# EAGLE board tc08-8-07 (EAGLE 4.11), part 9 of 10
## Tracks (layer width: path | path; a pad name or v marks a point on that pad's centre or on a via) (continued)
T_PWR_CLR\  (via drill 0.61) (continued)
  Top 0.254: v83.22,202.87 82.9,202.55 82.9,190.49 79.09,186.68 79.09,182.55 78.14,181.6 B23.K2 | v79.41,206.68 79.73,207 79.73,221.6 79.41,221.92 79.41,233.03 80.68,234.3 A23.R1 80.68,235.57 80.68,239.38 76.24,243.83 76.24,254.94 73.38,257.8 73.38,259.7 70.2,259.7 v67.98,257.48
  Bottom 0.254: v83.22,202.87 v79.41,206.68 | v67.98,257.48 65.76,257.48 A24.H2
T_REV\  (via drill 0.61)
  Top 0.254: v61.95,185.73 60.04,187.63 60.04,217.48 60.36,217.79 60.36,220.97 60.04,221.29 60.04,243.83 60.36,244.14 60.36,246.37 60.04,246.68 60.04,248.91 | 60.04,248.91 60.04,254.94 59.73,255.26 59.73,256.21 61.63,258.11 61.63,259.7 A24.F2 | 60.04,248.91 v59.73,248.91
  Bottom 0.254: v61.95,185.73 72.74,185.73 74.01,184.46 B23.J2 | v59.73,248.91 79.41,248.91 80.36,247.96 A23.L1
T_SINGLE_UNIT\  (via drill 0.61)
  Top 0.254: v22.58,150.48 21.94,151.12 21.94,208.9 22.26,209.22 22.26,220.97 21.94,221.29 21.94,241.61 v23.85,243.51 | v64.17,246.37 64.81,247 64.81,250.18 A24.K2
  Bottom 0.254: v22.58,150.48 87.35,150.48 94.02,157.15 98.14,157.15 99.41,158.42 B21.T2 | v23.85,243.51 26.07,243.51 26.39,243.19 55.6,243.19 58.77,246.37 v64.17,246.37
T_STOP\
  Top 0.254: B23.E2 78.14,194.3 79.09,195.25 79.09,199.38 79.73,200.01 79.73,203.82 82.27,206.36 82.27,219.7 85.44,222.87 85.44,224.78 85.76,225.09 85.76,240.02 85.44,240.33 85.44,258.75 84.49,259.7 84.49,262.88 A23.E1
  Bottom 0.254: A24.D2 62.27,266.05 62.27,262.24 82.59,262.24 83.54,263.19 A23.E1
T_TRK  (via drill 0.61)
  Top 0.254: v175.93,223.83 174.98,222.87 174.98,221.6 175.3,221.29 175.3,207.31 174.98,207 174.98,200.01 179.11,195.89 179.11,194.3 B15.E2 | D14.U1 198.16,22.85 198.16,27.93 D14.S1 198.79,29.2 199.74,30.15 199.74,53.01 | v178.47,101.27 178.15,100.95 v178.15,76.82 | v197.84,76.82 199.74,74.92 199.74,53.01 | v122.59,221.29 121.32,221.29 119.1,219.06 115.61,219.06 v115.61,218.11 | v111.8,214.62 112.11,214.3 112.11,206.05 110.21,204.14 v110.21,201.92 | v111.8,200.96 112.11,200.65 v112.11,198.43 | v103.86,195.89 101.95,195.89 101.95,166.36 102.59,165.72 102.59,165.09 v99.73,162.23 | v86.08,157.47 86.08,56.5 v88.3,54.28 | 199.74,53.01 v200.06,53.01
  Bottom 0.254: v175.93,223.83 175.61,223.51 142.91,223.51 141.64,224.78 A18.U2 140.69,225.09 139.1,223.51 134.97,223.51 132.43,220.97 122.91,220.97 v122.59,221.29 | v178.47,101.27 176.88,101.27 C15.R2 | v178.15,76.82 v197.84,76.82 | v115.61,218.11 112.11,214.62 v111.8,214.62 | v110.21,201.92 111.16,200.96 v111.8,200.96 | v112.11,198.43 109.26,195.57 104.18,195.57 v103.86,195.89 | v99.73,162.23 98.14,160.64 95.6,160.64 95.29,160.96 91.48,160.96 90.84,160.33 87.03,160.33 85.76,159.05 85.76,157.47 v86.08,157.47 | v88.3,54.28 89.89,52.69 129.89,52.69 130.21,53.01 134.02,53.01 134.34,52.69 199.74,52.69 v200.06,53.01
T_TRK\  (via drill 0.61)
  Top 0.254: v187.04,221.29 187.04,195.25 186.09,194.3 B15.E1
  Bottom 0.254: v187.04,221.29 186.73,220.97 139.74,220.97 138.78,221.92 A18.V2
T_WRITE_OK\  (via drill 0.61)
  Top 0.254: v62.27,251.45 62.27,248.27 A24.L2 | v95.92,178.11 95.6,178.42 95.6,255.26 v94.65,256.21
  Bottom 0.254: v62.27,251.45 64.17,253.35 67.03,253.35 67.66,252.72 77.82,252.72 81,255.89 88.94,255.89 89.89,256.85 A22.H2 91.16,256.85 94.02,256.85 v94.65,256.21 | v95.92,178.11 93.7,175.88 76.87,175.88 75.28,177.47 B23.L2
TIM  (via drill 0.61)
  Top 0.254: v65.44,223.51 67.03,221.92 67.03,221.6 69.89,218.74 71.79,218.74 v71.79,218.11 | v99.41,225.73 99.1,226.05 99.1,227.64 98.78,227.95 98.78,238.11 v99.1,238.43 | v101.95,241.29 101.95,246.37 v102.59,247 | v140.37,247.96 140.05,248.27 140.05,264.15 142.91,267 142.91,271.45 139.74,274.62 139.74,277.48 141.32,279.07 v141.32,296.22 | v143.23,296.22 144.18,297.17 220.7,297.17 v220.7,282.24 | v233.08,282.24 233.72,281.61 v233.72,276.85 | v239.43,276.85 241.97,279.39 v241.97,284.47 | v251.5,285.1 252.45,286.05 254.04,286.05 254.04,275.26 v254.35,274.94 | v257.21,272.09 257.21,268.28 v256.58,267.64
  Route2 0.254: v101.95,241.29 v99.1,238.43 | v254.35,274.94 v257.21,272.09
  Route15 0.254: v89.89,219.7 92.43,222.24 92.43,222.87 v93.38,223.83 | v256.58,267.64 256.58,267 261.34,262.24 262.29,262.24 262.93,261.61 262.93,260.02 263.56,259.38 263.56,258.43 267.05,254.94 267.05,253.99 269.59,251.45 269.59,249.86 271.18,248.27 A08.L1
  Bottom 0.254: v65.44,223.51 61,223.51 59.41,225.09 A25.U1 | v71.79,218.11 72.11,218.43 88.62,218.43 v89.89,219.7 | v93.38,223.83 93.7,224.14 97.83,224.14 v99.41,225.73 | v102.59,247 102.91,246.68 105.45,246.68 105.76,246.37 138.78,246.37 v140.37,247.96 | v143.23,296.22 v141.32,296.22 | v233.08,282.24 v220.7,282.24 | v233.72,276.85 235.62,274.94 237.53,274.94 v239.43,276.85 | v241.97,284.47 242.29,284.15 250.54,284.15 v251.5,285.1
TIM\  (via drill 0.61)
  Top 0.254: v254.35,242.56 252.77,244.14 252.77,247 A09.L2 | v321.98,179.37 321.03,178.42 321.03,177.15 321.98,176.2 321.98,172.07 B04.N1 | v292.45,208.27 291.18,209.54 291.18,220.97 291.82,221.6 291.82,223.51 290.23,225.09 v290.23,226.36 | v288.33,228.27 288.64,228.59 288.64,233.99 288.33,234.3 288.33,235.57 v287.37,236.52
  Route2 0.254: v297.22,206.05 293.72,209.54 v292.45,208.27
  Route15 0.254: v321.98,179.37 318.81,179.37 311.5,186.68 311.5,187.63 310.55,188.58 309.6,188.58 298.8,199.38 298.8,204.46 v297.22,206.05
  Bottom 0.254: v254.35,242.56 272.45,242.56 274.04,244.14 A08.M1 274.99,243.83 275.63,243.83 275.63,240.33 277.53,238.43 278.17,238.43 279.75,236.84 287.06,236.84 v287.37,236.52 | v290.23,226.36 v288.33,228.27
TM_EN  (via drill 0.61)
  Top 0.254: v171.17,99.68 171.17,108.89 172.76,110.48 C16.M1 | B18.R2 137.83,165.72 136.88,166.68 136.88,184.77 136.24,185.41 136.24,202.55 136.56,202.87 136.56,205.09 136.88,205.41 136.88,233.35 137.83,234.3 A18.R2 | v121.96,103.18 121,104.13 121,120 121.64,120.64 121.64,122.54 121,123.18 121,162.55 v121.96,163.5
  Bottom 0.254: 178.79,99.68 180.69,99.68 181.96,98.41 C15.S1 | 178.79,99.68 v171.17,99.68 165.77,99.68 164.18,101.27 C16.R2 162.91,101.27 162.28,100.63 158.15,100.63 157.83,100.32 128.62,100.32 125.77,103.18 v121.96,103.18 | 178.79,99.68 183.23,104.13 184.19,104.13 184.82,103.49 201.01,103.49 204.82,107.3 207.05,107.3 207.36,107.62 C13.N1 | v121.96,163.5 122.27,163.18 133.07,163.18 134.66,164.77 137.51,164.77 B18.R2
TM_EN\  (via drill 0.61)
  Top 0.254: v209.9,115.56 209.9,110.48 210.54,109.84 210.54,105.72 210.86,105.4 C13.P1 | v221.97,117.46 221.97,128.89 222.6,129.53 222.6,134.93 223.56,135.88 C12.C1 | D15.K2 178.79,47.93 176.57,50.15 D15.J2 175.93,51.42 175.61,51.74 175.61,55.87 174.98,56.5 174.98,70.47 176.25,71.74 176.25,86.98 174.98,88.25 174.98,118.73 | 174.98,118.73 174.98,140.32 175.3,140.64 175.3,151.43 174.98,151.75 174.98,195.25 175.93,196.2 B15.D2 | 174.98,118.73 v175.61,118.73
  Bottom 0.254: v209.9,115.56 210.54,116.19 212.44,116.19 | 212.44,116.19 213.71,116.19 214.98,117.46 C12.K2 v221.97,117.46 | B15.D2 176.88,196.52 181.96,196.52 B15.D1 | 212.44,116.19 212.44,119.69 210.54,119.69 210.22,120 209.27,120 208,118.73 201.65,118.73 199.11,116.19 182.6,116.19 180.06,118.73 v175.61,118.73
TP00  (via drill 0.61)
  Top 0.254: B10.N1 245.78,172.07 244.19,173.66 244.19,185.73 243.24,186.68 B10.H2 | 206.73,197.15 202.28,197.15 B13.D2 | 206.73,197.15 206.73,199.38 208,200.65 B13.B1 | v183.55,130.16 183.87,130.48 183.87,158.1 184.19,158.42 184.19,160.64 183.87,160.96 183.87,182.55 182.92,183.5 B15.J1 182.6,188.58 181.33,189.85 181.33,203.82 182.6,205.09 182.6,220.33 181.33,221.6 181.33,227.95 181.01,228.27 181.01,239.7 181.33,240.02 181.33,244.46 v181.65,244.78 | v206.73,188.27 206.73,197.15 | A16.P2 166.09,238.43 163.87,240.65 A16.N2 164.18,241.61 166.41,243.83 A16.M2 | v181.65,244.78 181.65,246.37 182.28,247 A15.L1 | v187.36,283.2 187.04,282.88 187.04,268.59 181.96,263.51 181.96,261.61 181.33,260.97 181.33,245.1 v181.65,244.78 | v271.5,281.29 A08.B1
  Bottom 0.254: B10.H2 242.29,187.63 240.07,189.85 B10.F2 239.11,190.17 237.53,188.58 212.76,188.58 211.81,187.63 B13.H1 210.54,186.99 208,186.99 | 208,186.99 207.68,186.99 206.09,185.41 184.19,185.41 183.23,184.46 B15.J1 | v183.55,130.16 C15.E1 | 208,186.99 v206.73,188.27 | v181.65,244.78 180.06,243.19 168.31,243.19 167.36,244.14 A16.M2 | v271.5,281.29 271.18,280.98 238.16,280.98 234.99,284.15 234.35,284.15 234.03,283.83 218.79,283.83 218.48,283.51 211.49,283.51 210.86,282.88 187.68,282.88 v187.36,283.2
TP00\  (via drill 0.61)
  Top 0.254: 185.46,256.53 185.46,251.45 A15.K1 | 185.46,256.53 183.23,254.3 A15.J1 | 185.46,256.53 A15.H1 185.14,257.48 182.92,259.7 A15.F1 183.23,260.66 185.46,262.88 A15.E1 | v206.09,147.31 206.09,166.36 207.68,167.95 207.68,170.8 B13.N1 | CD18.AN1 144.82,108.57 145.77,109.52 v145.77,147.31 v145.77,151.12 | v171.49,253.35 171.17,253.04 171.17,233.03 164.82,226.68 164.82,218.43 v164.5,218.11 | v157.83,210.81 155.29,208.27 155.29,197.79 152.75,195.25 152.75,153.02 v153.07,152.71
  Bottom 0.254: v145.77,147.31 146.09,146.99 191.17,146.99 191.49,147.31 v206.09,147.31 | v171.49,253.35 172.12,252.72 181.01,252.72 181.96,253.67 A15.J1 | v164.5,218.11 157.83,211.44 v157.83,210.81 | v153.07,152.71 151.48,151.12 v145.77,151.12
TP00_A  (via drill 0.61)
  Top 0.254: v216.89,140.64 216.89,139.37 215.94,138.42 215.94,136.2 218.16,133.97 218.16,131.11 217.84,130.8 C12.E2 | v241.97,165.4 244.51,167.95 v244.51,170.49 | v256.58,177.47 256.89,177.79 v256.89,183.82 | v229.59,222.55 229.91,222.24 v229.91,217.16 | v233.08,216.84 233.72,216.21 v233.72,205.73
  Route2 0.254: v220.38,143.5 241.97,165.09 v241.97,165.4 | v253.4,174.3 v256.58,177.47
  Route15 0.254: v229.59,222.55 v221.02,231.13 | v233.72,205.73 237.53,201.92 237.53,200.96 247.37,191.12 247.37,189.54 248.96,187.95 B10.H1
  Bottom 0.254: v216.89,140.64 217.52,141.27 217.84,141.27 220.06,143.5 v220.38,143.5 | v244.51,170.49 244.83,170.17 249.27,170.17 v253.4,174.3 | v256.89,183.82 256.26,184.46 254.04,184.46 251.5,186.99 249.91,186.99 B10.H1 | v221.02,231.13 220.38,231.13 219.75,230.49 197.84,230.49 197.52,230.81 194.66,230.81 194.35,230.49 187.36,230.49 186.41,231.45 A15.S1 | v229.91,217.16 230.22,216.84 v233.08,216.84
TP00_A\  (via drill 0.61)
  Top 0.254: A15.P1 185.46,238.75 185.46,243.83 A15.M1 | A15.R1 182.28,235.57 182.28,240.65 A15.N1 | v163.55,243.51 A16.L2
  Bottom 0.254: v163.55,243.51 164.5,242.56 181.01,242.56 181.96,241.61 A15.N1 183.23,241.61 185.46,243.83 A15.M1
TP0_XTLK_DY\  (via drill 0.61)
  Top 0.254: A16.J2 163.87,253.35 166.09,251.13 A16.K2 167.04,250.18 167.99,249.23 167.99,233.35 v168.31,233.03 | v176.25,255.58 A15.F2
  Bottom 0.254: v176.25,255.58 175.93,255.26 165.14,255.26 164.18,254.3 A16.J2 | v168.31,233.03 220.7,233.03 221.97,234.3 226.1,234.3 226.41,234.62 A11.R2
TP01  (via drill 0.61)
  Top 0.254: v184.19,238.43 184.5,238.75 v184.5,246.68 | v172.44,58.41 174.34,58.41 174.34,70.79 175.61,72.06 175.61,86.66 174.34,87.94 v174.34,140.96 174.34,148.58 171.8,151.12 171.8,159.69 167.04,164.45 167.04,167.63 B16.P2 166.41,168.9 166.41,173.98 B16.M2 | v215.94,122.22 215.62,122.54 215.62,135.56 215.3,135.88 215.3,138.74 215.94,139.37 v215.94,139.69 | v165.45,236.21 161.64,236.21 161.64,188.27 162.91,186.99 162.91,185.41 162.28,184.77 162.28,173.02 163.23,172.07 B16.N2
  Bottom 0.254: v184.19,238.43 180.06,238.43 A15.P2 178.79,237.8 177.84,236.84 171.17,236.84 170.53,236.21 v165.45,236.21 | v184.5,246.68 186.73,248.91 200.06,248.91 203.24,252.08 208.95,252.08 210.22,253.35 214.03,253.35 A12.J2 | v172.44,58.41 146.09,58.41 145.13,57.46 CD18.BF1 | B16.N2 163.87,170.8 166.09,168.58 B16.P2 | v174.34,140.96 176.88,140.96 177.2,140.64 181.33,140.64 181.96,140.01 C15.B1 183.23,140.01 184.19,140.96 189.58,140.96 189.9,140.64 192.76,140.64 193.08,140.96 202.28,140.96 202.6,140.64 206.09,140.64 206.41,140.96 214.98,140.96 215.3,140.64 215.94,140.64 v215.94,139.69 | v215.94,122.22 221.02,122.22 221.97,121.27 226.1,121.27 226.41,120.96 C11.J2
TP01\  (via drill 0.61)
  Top 0.254: 177.52,242.24 179.11,243.83 A15.M2 A15.K2 | 177.52,242.24 176.88,241.61 A15.N2 175.93,241.92 175.93,247 A15.L2 175.93,248.27 175.93,253.35 A15.J2 | v181.33,179.06 180.69,179.69 180.69,196.84 177.84,199.7 177.84,224.14 177.52,224.46 177.52,242.24
  Bottom 0.254: v181.33,179.06 195.93,179.06 197.2,177.79 B13.L2
TP01_A  (via drill 0.61)
  Top 0.254: v125.77,105.72 124.18,107.3 124.18,147.62 v124.81,148.26 | v144.18,147.31 143.86,147.62 143.86,151.12 143.23,151.75 143.23,163.18 | 143.23,163.18 143.23,167.95 142.59,168.58 142.59,199.38 143.23,200.01 v143.23,224.78 | v179.42,106.67 C15.M2 | v214.03,163.18 214.03,159.37 B12.T2 | v180.38,169.85 180.69,169.53 180.69,166.99 v179.74,166.04 | 143.23,163.18 v144.82,163.18
  Route15 0.254: v214.03,163.18 212.44,163.18 v203.87,171.76
  Bottom 0.254: v179.42,106.67 178.79,106.03 172.12,106.03 168.95,102.86 128.62,102.86 v125.77,105.72 | v124.81,148.26 135.29,148.26 136.24,147.31 v144.18,147.31 | v143.23,224.78 143.86,224.14 174.98,224.14 175.61,224.78 176.25,224.78 176.88,224.14 176.88,222.87 176.57,222.87 A15.V2 | v203.87,171.76 202.28,170.17 190.54,170.17 189.9,169.53 180.69,169.53 v180.38,169.85 | v179.74,166.04 178.15,164.45 177.52,164.45 176.88,163.82 167.36,163.82 166.72,163.18 v144.82,163.18
TP01_A\  (via drill 0.61)
  Top 0.254: A15.U2 179.11,226.05 179.11,231.13 A15.S2 | v173.71,179.06 174.34,179.69 174.34,209.86 174.66,210.17 174.66,220.97 174.34,221.29 174.34,223.51 175.93,225.09 175.93,227.95 A15.T2 175.93,229.22 175.93,234.3 A15.R2
  Bottom 0.254: v173.71,179.06 165.14,179.06 164.18,178.11 B16.L2 | A15.S2 179.11,231.13 176.88,228.9 A15.T2
TP1_XTLK_DY\  (via drill 0.61)
  Top 0.254: B16.H2 166.41,186.68 164.18,184.46 B16.J2 163.55,188.58 162.28,189.85 162.28,232.08 v163.55,233.35 | v208.32,224.78 206.09,227 v206.09,234.3 v206.09,271.13
  Route15 0.254: v220.38,224.78 221.65,223.51 222.6,223.51 223.56,222.55 226.41,222.55 A11.V2
  Bottom 0.254: v220.38,224.78 219.75,224.14 208.95,224.14 v208.32,224.78 | v206.09,271.13 192.76,271.13 192.12,271.77 188,271.77 187.04,272.72 183.23,272.72 A15.B1 | v163.55,233.35 163.87,233.67 167.68,233.67 167.99,233.99 168.95,233.99 169.26,233.67 205.46,233.67 v206.09,234.3
TS03\  (via drill 0.61)
  Top 0.254: D17.H2 153.71,53.33 153.71,48.25 D17.K2 | v324.2,113.97 324.2,115.88 325.16,116.83 C04.K1 | v308.33,43.17 308.33,38.72 308.01,38.4 308.01,37.77 308.33,37.45 308.33,32.37 308.01,32.06 308.01,25.71 304.84,22.53 304.84,21.89 305.79,20.94 v305.79,19.67 | v179.74,38.4 178.15,39.99 178.15,42.85 179.74,44.44 179.74,45.07 179.11,45.71 171.17,45.71 171.17,43.17 v169.58,41.58 | v167.04,44.12 165.14,46.03 v165.14,49.83 | v160.69,51.1 v158.15,53.64
  Route2 0.254: v274.36,16.18 269.28,16.18 266.74,18.72 265.78,17.77 256.58,17.77 252.13,22.21 v248.32,18.4 | v182.28,40.95 v179.74,38.4 | v169.58,41.58 v167.04,44.12
  Route15 0.254: v324.2,113.97 324.52,113.97 329.92,108.57 329.92,104.13 331.82,102.22 331.82,100.32 336.59,95.55 336.59,84.76 v337.22,84.13 | v331.19,77.77 331.19,75.87 321.03,65.71 321.03,64.76 317.22,60.95 316.9,61.27 316.27,61.27 305.79,50.79 v306.74,49.83 | v241.34,19.35 237.21,23.48 232.45,23.48 226.73,29.2 225.46,29.2 221.65,33.01 210.86,33.01 201.33,42.53 197.2,42.53 v196.89,42.21
  Bottom 0.254: D17.K2 153.39,47.93 151.17,50.15 D17.J2 | v337.22,84.13 336.9,83.81 333.09,83.81 331.51,82.22 331.51,80 330.87,79.36 330.87,77.77 v331.19,77.77 | v306.74,49.83 305.15,48.25 305.15,43.17 v308.33,43.17 | v305.79,19.67 303.25,17.13 283.25,17.13 282.61,16.5 274.67,16.5 v274.36,16.18 | v248.32,18.4 247.69,17.77 242.92,17.77 v241.34,19.35 | v196.89,42.21 196.57,42.53 184.82,42.53 183.23,40.95 v182.28,40.95 | v165.14,49.83 164.82,49.52 162.28,49.52 v160.69,51.1 | v158.15,53.64 154.66,53.64 D17.H2
U+M_DY\  (via drill 0.61)
  Top 0.254: D14.N1 194.98,38.72 193.39,40.31 193.39,58.72 192.44,59.68 D14.E2 191.81,60.95 191.81,63.81 v191.49,64.12 | v210.22,101.27 207.05,98.1 v207.05,97.46 | v204.19,95.55 203.55,94.92 203.55,88.57 v204.19,87.94 | v181.96,80.95 182.92,80 v182.92,72.69 | v224.19,139.37 224.19,142.23 C12.A1 | v229.91,131.75 v229.91,133.65
  Route2 0.254: v191.49,64.12 v182.92,72.69 | v229.91,131.75 219.43,121.27 219.43,114.92 216.25,111.75 216.25,108.89 215.94,108.57 215.94,103.49 214.67,102.22 C12.R2
  Route15 0.254: v204.19,87.94 203.24,87.94 198.79,83.49 198.79,82.54 v197.84,81.58 | v229.91,133.65 v224.19,139.37
  Bottom 0.254: v210.22,101.27 213.71,101.27 C12.R2 | v207.05,97.46 205.14,95.55 v204.19,95.55 | v197.84,81.58 196.57,82.86 182.6,82.86 181.96,82.22 v181.96,80.95
USR_00  (via drill 0.61)
  Top 0.254: v59.09,283.83 59.09,276.85 A25.A1 | v272.45,282.24 275.94,278.75 275.94,227.95 276.9,227 276.9,223.51 277.53,222.87 A07.V2 278.48,221.92 278.48,209.22 276.58,207.31 276.58,200.01 v278.17,198.43 | v281.98,192.08 282.29,192.39 282.29,197.15 v281.66,197.79
  Bottom 0.254: v59.09,283.83 59.41,283.51 134.02,283.51 135.61,285.1 140.69,285.1 141.01,284.79 184.82,284.79 186.09,286.05 188.63,286.05 189.27,285.42 209.59,285.42 210.22,286.05 212.76,286.05 213.4,286.69 216.89,286.69 217.84,285.74 231.18,285.74 231.81,286.37 235.3,286.37 240.07,281.61 270.55,281.61 271.18,282.24 v272.45,282.24 | v281.98,192.08 282.29,192.39 285.79,192.39 286.74,193.34 B07.E1 | v281.66,197.79 281.02,198.43 v278.17,198.43
USR_00\  (via drill 0.61)
  Top 0.254: v302.61,198.43 304.2,200.01 304.2,202.24 304.84,202.87 v304.84,203.19 | v284.2,195.25 B07.F1
  Bottom 0.254: v284.2,195.25 284.52,195.57 298.8,195.57 300.71,197.47 301.66,197.47 v302.61,198.43 | v304.84,203.19 304.84,204.46 331.82,204.46 333.41,206.05 337.54,206.05 B03.A1
USR_01  (via drill 0.61)
  Top 0.254: 279.12,192.71 280.39,191.44 280.39,188.27 280.71,187.95 B07.H2 | 279.12,192.71 279.12,206.05 279.44,206.36 279.44,206.68 281.02,208.27 A07.U2 | v75.92,290.82 69.57,290.82 64.49,295.9 64.49,296.22 60.04,296.22 55.92,292.09 55.92,280.34 56.23,280.02 56.23,273.99 55.92,273.67 A25.B1 | v80.68,295.58 94.97,295.58 94.97,296.22 95.6,296.85 129.58,296.85 129.58,281.61 132.12,279.07 v132.12,276.85 | v187.36,260.66 188.31,261.61 193.71,261.61 v193.71,257.48 | v196.89,257.48 197.84,258.43 200.06,258.43 v200.06,257.48 | v220.06,238.43 221.97,236.52 221.97,233.99 221.65,233.67 v221.65,232.4 | v251.81,210.17 253.4,210.17 254.04,209.54 258.8,209.54 v258.8,210.17 | v277.53,192.39 279.12,192.39 279.12,192.71
  Route2 0.254: v75.92,290.82 v80.68,295.58 | v249.27,212.08 251.5,209.86 v251.81,210.17
  Route15 0.254: v132.12,276.85 132.43,276.85 134.34,274.94 138.15,274.94 v140.69,272.4 | v166.09,273.67 168.95,276.53 178.15,267.32 178.47,267.32 184.82,260.97 v184.82,260.66 | v200.06,257.48 202.92,254.62 202.92,252.72 203.55,252.08 205.78,252.08 208.63,249.23 209.9,249.23 210.22,248.91 211.17,248.91 213.71,246.37 220.7,246.37 221.97,245.1 221.97,240.33 v220.06,238.43 | v221.65,232.4 221.02,232.4 219.75,231.13 220.7,230.18 221.02,230.18 228.32,222.87 228.32,220.02 v236.89,211.44 | v258.8,210.17 258.8,207.95 260.7,206.05 260.7,205.73 v271.82,194.61
  Bottom 0.254: v140.69,272.4 142.59,274.31 165.45,274.31 v166.09,273.67 | v184.82,260.66 v187.36,260.66 | v193.71,257.48 v196.89,257.48 | v236.89,211.44 237.21,211.12 248.32,211.12 v249.27,212.08 | v271.82,194.61 274.04,192.39 v277.53,192.39
USR_01\  (via drill 0.61)
  Top 0.254: v273.09,186.99 272.77,187.31 272.77,198.74 267.69,203.82 267.69,205.09 266.42,206.36 266.42,218.11 v267.69,219.38 | v304.84,219.7 307.69,222.55 v307.69,223.83 | v334.36,223.83 336.27,223.83 336.27,219.7 335.63,219.06 335.63,203.51 B03.B1
  Bottom 0.254: v273.09,186.99 274.04,186.04 275.63,186.04 277.21,184.46 B07.J2 | v267.69,219.38 268.01,219.7 v304.84,219.7 | v307.69,223.83 308.01,223.51 331.82,223.51 332.14,223.83 v334.36,223.83
USR_02  (via drill 0.61)
  Top 0.254: v280.07,195.25 279.75,194.93 279.75,193.03 282.29,190.49 282.29,180.01 283.88,178.42 B07.L1 | v272.45,200.33 272.77,200.65 272.77,208.27 v274.67,210.17 | v286.42,210.49 286.74,210.81 v286.74,222.24 | v67.98,270.81 74.97,277.8 79.73,277.8 v79.73,276.85 | v114.02,271.13 114.34,270.81 114.34,269.23 117.83,265.74 117.83,258.43 125.77,250.49 v126.72,250.49 | v160.06,247 163.55,250.49 v165.14,250.49
  Route2 0.254: v274.36,195.89 271.18,199.06 v272.45,200.33
  Route15 0.254: v81.63,275.58 81.95,275.58 83.86,273.67 86.08,273.67 88.62,276.21 90.21,274.62 91.48,274.62 v92.43,275.58 | v100.68,275.58 101.95,275.58 105.76,271.77 108.62,271.77 v108.94,271.45 | v126.72,250.49 127.04,250.49 128.31,249.23 133.7,249.23 135.93,247 136.88,247 137.51,246.37 140.05,246.37 v140.37,246.68 | v165.14,250.49 175.61,240.02 179.42,240.02 184.19,235.26 186.73,235.26 194.98,227 198.16,227 198.47,226.68 208,226.68 211.17,229.86 220.06,220.97 223.56,220.97 v228.64,215.89 | v236.89,214.93 242.29,220.33 246.42,216.21 247.05,216.21 253.4,209.86 254.35,209.86 v268.32,195.89
  Bottom 0.254: v280.07,195.25 279.75,195.57 274.67,195.57 v274.36,195.89 274.04,195.57 268.64,195.57 v268.32,195.89 | v274.67,210.17 274.99,210.49 v286.42,210.49 | v286.74,222.24 A07.V1 | v67.98,270.81 67.66,271.13 60.36,271.13 59.41,270.18 A25.C1 | v79.73,276.85 81,275.58 v81.63,275.58 | v92.43,275.58 92.75,275.26 95.92,275.26 96.24,274.94 99.1,274.94 99.73,275.58 v100.68,275.58 | v108.94,271.45 109.26,271.13 v114.02,271.13 | v140.37,246.68 140.69,246.37 159.42,246.37 v160.06,247 | v228.64,215.89 227.68,214.93 227.68,213.03 234.99,213.03 v236.89,214.93
USR_02\
  Bottom 0.254: B07.M1 288.01,174.93 288.33,175.25 292.45,175.25 293.09,175.88 305.79,175.88 306.42,176.52 318.49,176.52 319.12,177.15 321.03,177.15 321.66,176.52 336.59,176.52 342.62,182.55 342.62,187.31 341.03,187.31 338.17,190.17 335.63,190.17 B03.F1
UTS  (via drill 0.61)
  Top 0.254: v179.74,96.83 180.38,96.19 180.38,93.02 180.69,92.7 v180.69,84.76 | v174.66,84.76 174.66,79.05 171.8,76.19 166.72,76.19 v166.72,76.82 | v8.29,75.87 8.61,76.19 8.61,179.37 | v8.61,252.08 8.61,179.37 | v186.09,170.8 186.09,168.9 B15.P1 | v191.17,171.76 190.85,172.07 190.85,175.25 v192.44,176.83 | v190.54,177.79 190.22,178.11 v190.22,180.96 | 8.61,179.37 v8.29,179.37 | v194.98,268.91 191.49,272.4 191.49,273.67 188,277.17 188,282.56 188.31,282.88 188.31,283.51 176.88,294.94 147.04,294.94 147.04,295.58 146.4,296.22 v144.5,296.22 | v53.06,292.09 44.17,283.2 44.17,263.51 41.63,260.97 41.63,255.58 42.58,254.62 A26.J1
  Route2 0.254: v179.74,96.83 v182.28,99.36
  Route15 0.254: v245.78,263.83 245.46,263.83 243.88,265.42 242.92,265.42 v236.89,271.45 | v229.59,273.36 v227.68,275.26
  Bottom 0.254: v182.28,99.36 182.6,99.68 186.73,99.68 188.31,101.27 C14.R2 | v174.66,84.76 v180.69,84.76 | v166.72,76.82 159.74,76.82 159.42,77.14 158.79,77.14 157.52,75.87 v8.29,75.87 | v8.61,252.08 9.56,253.04 10.2,253.04 10.51,252.72 41.31,252.72 42.26,253.67 A26.J1 | v186.09,170.8 186.73,170.17 189.58,170.17 v191.17,171.76 | v192.44,176.83 191.49,177.79 v190.54,177.79 | v190.22,180.96 188.95,182.23 170.53,182.23 167.99,179.69 127.67,179.69 127.35,180.01 123.23,180.01 122.91,179.69 41.63,179.69 41.31,180.01 40.68,180.01 40.36,179.69 8.61,179.69 v8.29,179.37 | v245.78,263.83 248.64,263.83 A10.E1 | v236.89,271.45 236.57,271.77 232.76,271.77 231.18,273.36 v229.59,273.36 | v227.68,275.26 227.37,274.94 224.51,274.94 221.02,271.45 215.62,271.45 212.76,268.59 195.3,268.59 v194.98,268.91 | v144.5,296.22 143.55,297.17 132.75,297.17 130.85,295.26 130.53,295.26 128.94,293.68 102.91,293.68 102.27,294.31 98.46,294.31 97.19,293.04 82.27,293.04 81.63,292.41 59.09,292.41 58.46,293.04 54.01,293.04 v53.06,292.09
UTS\  (via drill 0.61)
  Top 0.254: C16.A1 172.76,142.23 172.76,137.15 C16.C1 172.76,135.88 172.44,135.56 172.44,133.02 169.58,130.16 | 169.58,130.16 169.58,127.62 C16.F1 169.58,126.35 169.58,121.27 C16.J1 170.22,120 172.44,117.78 C16.K1 172.76,118.1 172.76,123.18 C16.H1 | 169.58,130.16 169.58,132.7 C16.D1 169.58,133.97 169.58,139.05 C16.B1 | v178.47,115.56 178.15,115.24 178.15,106.35 179.11,105.4 C15.P2
  Bottom 0.254: C15.P2 180.06,105.08 181.01,106.03 187.68,106.03 188.95,104.76 C14.P2 192.76,105.08 193.71,106.03 202.6,106.03 209.59,113.02 212.76,113.02 213.71,113.97 C12.L2 | v178.47,115.56 175.3,115.56 173.71,117.14 C16.K1
VCC  (via drill 0.61)
  Top 0.635: D11.A2 229.91,73.65 229.59,73.97 229.59,90.47 228.64,91.43 228.64,138.1 230.22,139.69 C11.A2 | AB01.AE1 363.26,262.88 363.26,257.8 AB01.AH1 | AB01.AL1 AB01.AJ1 | AB01.AF1 360.08,260.97 360.08,266.05 AB01.AD1 360.08,267.32 360.08,272.4 AB01.AB1 | AB01.BE1 362.94,193.98 360.72,196.2 AB01.BD1 AB01.BB1 | AB01.BE1 AB01.BC1 363.89,200.65 363.89,201.28 365.48,202.87 365.48,244.78 363.89,246.37 363.89,250.18 AB01.AK1 | v281.66,279.39 281.66,277.17 281.34,276.85 A07.A2 | C01.A2 357.86,143.18 365.48,150.8 365.48,188.58 363.57,190.49 AB01.BE1
  Bottom 0.635: CD18.BA2 141.96,73.33 143.23,74.6 149.58,74.6 150.85,73.33 153.39,73.33 D17.A2 154.66,73.33 156.25,74.92 165.45,74.92 166.72,73.65 D16.A2 167.36,73.33 168.63,74.6 177.52,74.6 177.68,74.44 | 177.68,74.44 178.79,73.33 D15.A2 | 190.38,74.44 190.22,74.6 177.84,74.6 177.68,74.44 | 190.38,74.44 191.49,73.33 D14.A2 | 190.38,74.44 190.54,74.6 199.11,74.6 199.74,73.97 203.55,73.97 204.19,73.33 D13.A2 205.46,73.33 206.09,73.97 209.9,73.97 210.54,74.6 213.4,74.6 214.67,73.33 216.89,73.33 D12.A2 218.16,73.33 219.43,74.6 225.46,74.6 227.05,73.01 D11.A2 230.86,73.33 232.13,74.6 241.02,74.6 242.29,73.33 D10.A2 243.56,73.33 245.15,74.92 250.86,74.92 252.45,73.33 254.99,73.33 D09.A2 256.26,73.33 257.85,74.92 266.1,74.92 267.69,73.33 D08.A2 268.96,73.33 270.23,74.6 279.12,74.6 280.39,73.33 D07.A2 | 152.28,144.29 153.39,143.18 C17.A2 | 152.28,144.29 152.12,144.45 143.23,144.45 141.96,143.18 CD18.AA2 | 152.28,144.29 152.44,144.45 164.82,144.45 166.09,143.18 C16.A2 167.36,143.18 168.63,144.45 177.52,144.45 178.79,143.18 C15.A2 180.06,143.18 181.65,144.77 188,144.77 189.58,143.18 191.49,143.18 C14.A2 192.76,143.18 194.03,144.45 202.92,144.45 203.08,144.29 | 203.08,144.29 204.19,143.18 C13.A2 | 203.08,144.29 203.24,144.45 215.62,144.45 216.89,143.18 C12.A2 218.16,143.18 219.75,144.77 228,144.77 229.59,143.18 C11.A2 230.86,143.18 231.18,143.5 234.99,143.5 236.26,144.77 241.65,144.77 242.92,143.5 C10.A2 243.56,143.18 244.83,144.45 250.86,144.45 252.45,142.86 C09.A2 256.26,143.18 256.58,143.18 257.85,144.45 266.42,144.45 267.69,143.18 C08.A2 268.96,143.18 270.55,144.77 278.8,144.77 280.39,143.18 C07.A2 281.66,143.18 283.25,144.77 291.5,144.77 293.09,143.18 C06.A2 294.36,143.18 295.63,144.45 304.2,144.45 305.47,143.18 305.79,143.18 C05.A2 307.06,143.18 308.01,143.18 309.28,144.45 313.41,144.45 314.68,143.18 318.49,143.18 C04.A2 319.76,143.18 321.03,144.45 327.7,144.45 328.97,143.18 331.19,143.18 C03.A2 332.46,143.18 333.73,144.45 342.62,144.45 342.78,144.29
  Bottom 0.635: 342.78,144.29 343.89,143.18 C02.A2 | C01.A2 356.59,143.18 355.32,144.45 342.94,144.45 342.78,144.29 | 240.86,277.96 240.7,278.12 232.45,278.12 230.86,276.53 A11.A2 229.59,276.53 228.64,276.53 227.37,277.8 219.43,277.8 218.16,276.53 A12.A2 216.89,276.53 215.62,277.8 194.03,277.8 192.76,276.53 A14.A2 191.49,276.53 187.68,276.53 186.09,278.12 181.65,278.12 180.06,276.53 A15.A2 178.79,276.53 177.52,277.8 170.22,277.8 168.95,276.53 167.36,276.53 A16.A2 166.09,276.53 164.82,277.8 143.23,277.8 141.96,276.53 A18.A2 140.69,276.53 139.1,278.12 118.15,278.12 116.56,276.53 A20.A2 115.29,276.53 114.02,277.8 101.64,277.8 101.48,277.64 | 240.86,277.96 242.29,276.53 A10.A2 | 253.56,277.96 253.4,278.12 241.02,278.12 240.86,277.96 | 253.56,277.96 254.99,276.53 A09.A2 | 253.56,277.96 253.72,278.12 266.74,278.12 268.01,276.85 A08.A2 268.96,276.53 270.23,277.8 275.31,277.8 276.26,276.85 280.07,276.85 280.39,276.53 A07.A2 | A23.A2 78.14,276.85 78.14,278.12 87.98,278.12 89.57,276.53 89.89,276.53 A22.A2 91.16,276.53 92.43,277.8 101.32,277.8 101.48,277.64 | 101.48,277.64 102.59,276.53 A21.A2 | 101.48,207.79 102.59,206.68 B21.A2 | 101.48,207.79 101.32,207.95 92.43,207.95 91.16,206.68 B22.A2 | 101.48,207.79 101.64,207.95 114.02,207.95 115.29,206.68 B20.A2 116.56,206.68 118.15,208.27 139.1,208.27 140.69,206.68 B18.A2 141.96,206.68 143.55,208.27 162.28,208.27 164.18,206.36 B16.A2 170.85,206.36 172.44,207.95 177.52,207.95 178.79,206.68 B15.A2 180.06,206.68 181.33,207.95 187.36,207.95 188.95,206.36 B14.A2 192.76,206.68 194.35,208.27 203.55,208.27 204.03,207.79
  Bottom 0.635: 204.03,207.79 204.82,207 B13.A2 | 204.03,207.79 204.19,207.95 215.62,207.95 216.89,206.68 B12.A2 218.16,206.68 220.38,206.68 221.97,208.27 228.64,208.27 229.91,207 B11.A2 230.86,206.68 232.13,207.95 241.02,207.95 242.29,206.68 B10.A2 243.56,206.68 247.37,206.68 248.96,208.27 254.04,208.27 255.31,207 B09.A2 256.26,206.68 257.53,207.95 265.47,207.95 266.74,206.68 267.69,206.68 B08.A2 268.96,206.68 270.55,208.27 278.8,208.27 280.39,206.68 B07.A2 281.66,206.68 282.93,207.95 290.87,207.95 292.14,206.68 293.09,206.68 B06.A2 294.36,206.68 295.63,207.95 302.93,207.95 304.52,206.36 B05.A2 306.74,207 308.01,208.27 315.95,208.27 317.54,206.68 318.49,206.68 B04.A2 321.66,206.36 323.25,207.95 329.92,207.95 331.19,206.68 B03.A2 332.46,206.68 333.73,207.95 340.4,207.95 341.98,206.36 B02.A2 345.16,206.68 346.43,207.95 354.37,207.95 355.64,206.68 356.59,206.68 AB01.BA2 357.54,205.73 359.76,203.51 AB01.BB1 | AB01.AB1 359.76,273.36 357.54,275.58 AB01.AA2 356.59,276.53 355.32,277.8 348.02,277.8 346.43,279.39 v281.66,279.39 | AB01.AD1 361.03,267 363.26,269.23 AB01.AC1 | AB01.AL1 361.03,247.96 363.26,250.18 AB01.AK1 | AB01.AJ1 361.03,254.3 363.26,256.53 AB01.AH1 362.94,257.48 360.72,259.7 AB01.AF1
W01  (via drill 0.61)
  Top 0.254: v31.15,255.58 31.47,255.26 31.47,234.3 30.52,233.35 v30.52,230.81 | v27.34,222.55 v27.34,218.43 | v39.72,209.54 38.45,208.27 38.45,199.38 v40.04,197.79 | v39.72,178.74 40.99,177.47 40.99,147.31 41.63,146.67 41.63,75.24 v43.22,73.65 | v137.83,46.34 137.83,50.15 CD18.BJ2
  Route2 0.254: v30.52,230.81 32.42,228.9 28.93,225.41 28.93,224.14 v27.34,222.55 | v36.87,181.6 v39.72,178.74
  Bottom 0.254: v31.15,255.58 34.64,255.58 35.91,254.3 A26.J2 | v27.34,218.43 30.2,215.57 38.77,215.57 39.72,214.62 v39.72,209.54 | v40.04,197.79 40.04,194.93 39.09,194.93 37.82,193.66 37.82,181.6 v36.87,181.6 | v43.22,73.65 70.52,46.34 v137.83,46.34
W02  (via drill 0.61)
  Top 0.254: v38.77,259.38 38.45,259.07 38.45,252.4 39.41,251.45 A26.K2 | v27.34,259.07 25.75,259.07 25.75,246.05 24.8,245.1 24.8,242.24 25.12,241.92 25.12,231.76 v23.53,230.18 | v20.99,222.55 21.31,222.24 v21.31,218.43 | v76.87,189.22 76.55,188.9 76.55,180.33 v78.78,178.11 | v83.86,176.83 82.59,175.56 v82.59,171.12 | v71.16,163.82 70.2,162.86 70.2,147.31 v74.01,143.5 | v102.27,128.26 101.95,127.94 101.95,89.84 v107.03,84.76 | v114.97,76.82 114.65,76.5 114.65,27.93 124.5,18.09 124.5,13.32 125.13,12.69 137.51,12.69 137.51,18.72 CD18.BV2
  Route2 0.254: v23.53,230.18 22.58,229.22 22.58,224.14 v20.99,222.55
  Bottom 0.254: v38.77,259.38 38.45,259.07 v27.34,259.07 | v21.31,218.43 24.8,214.93 38.45,214.93 39.09,214.3 39.09,210.17 35.6,210.17 34.96,209.54 34.96,205.09 42.26,205.09 42.9,205.73 43.85,205.73 46.39,203.19 47.34,203.19 61.31,189.22 v76.87,189.22 | v78.78,178.11 80.36,176.52 83.54,176.52 v83.86,176.83 | v82.59,171.12 82.59,166.36 78.46,166.36 75.92,163.82 v71.16,163.82 | v74.01,143.5 89.25,128.26 v102.27,128.26 | v107.03,84.76 v114.97,76.82
W03  (via drill 0.61)
  Top 0.254: v29.88,213.03 30.2,212.71 v30.2,207 | v11.47,192.39 10.83,193.03 v10.83,194.61 | v48.61,76.82 49.88,75.55 v49.88,73.65 | v115.92,68.25 v118.46,68.25 | v141.01,63.17 141.01,60.95 CD18.BE2
  Route2 0.254: v138.15,66.03 v141.01,63.17
  Route15 0.254: v10.83,226.36 v16.55,220.65
  Bottom 0.254: v10.83,226.36 9.88,226.36 9.88,236.52 16.55,243.19 21.31,243.19 24.8,246.68 28.61,246.68 28.93,246.37 34.96,246.37 35.91,247.32 A26.L2 | v16.55,220.65 18.13,219.06 19.4,219.06 25.44,213.03 v29.88,213.03 | v30.2,207 15.59,192.39 v11.47,192.39 | v10.83,194.61 6.7,190.49 6.7,103.49 13.69,103.49 40.36,76.82 v48.61,76.82 | v49.88,73.65 55.6,67.93 115.61,67.93 v115.92,68.25 | v118.46,68.25 118.78,67.93 136.24,67.93 v138.15,66.03
W04  (via drill 0.61)
  Top 0.254: v38.77,233.35 38.45,233.67 38.45,238.75 39.72,240.02 A26.M2 | v30.52,220.65 30.83,220.33 v30.83,213.98 | v24.17,212.08 23.85,211.76 v23.85,206.36 | v17.18,150.8 18.13,149.85 18.13,140.96 18.77,140.32 v18.77,135.24
  Route2 0.254: v36.87,231.45 36.87,230.81 35.28,229.22 35.28,225.41 v30.52,220.65
  Bottom 0.254: v36.87,231.45 v38.77,233.35 | v30.83,213.98 30.83,212.08 v24.17,212.08 | v23.85,206.36 7.34,189.85 7.34,150.8 v17.18,150.8 | v18.77,135.24 60.04,93.97 122.27,93.97 124.81,96.51 136.56,96.51 137.51,95.55 CD18.AT2
W05  (via drill 0.61)
  Top 0.254: v130.21,40.31 133.07,40.31 133.07,32.37 141.01,24.44 141.01,22.85 CD18.BU2
  Route2 0.254: v10.83,230.18 v1.94,221.29
  Bottom 0.254: v10.83,230.18 12.42,230.18 12.42,238.11 16.86,242.56 24.48,242.56 25.44,241.61 27.66,241.61 29.25,240.02 34.96,240.02 35.91,240.97 A26.N2 | v1.94,221.29 1.94,61.58 35.6,61.58 51.47,45.71 63.54,45.71 69.25,39.99 129.89,39.99 v130.21,40.31
W06  (via drill 0.61)
  Top 0.254: v11.47,218.43 11.78,218.11 11.78,204.46 13.05,203.19 13.05,151.43 15.59,148.89 15.59,139.69 v17.18,138.1
  Route15 0.254: v14.64,227.95 v17.5,225.09 | v135.29,108.25 v137.83,110.8
  Bottom 0.254: v14.64,227.95 13.05,227.95 13.05,234.94 15.28,237.16 15.91,237.16 16.23,236.84 38.14,236.84 39.09,237.8 A26.P2 | v17.5,225.09 14.32,221.92 14.32,218.43 v11.47,218.43 | v17.18,138.1 48.61,106.67 133.7,106.67 v135.29,108.25 | v137.83,110.8 140.69,110.8 CD18.AM2
W07  (via drill 0.61)
  Top 0.254: v140.69,120.64 140.69,118.41 141.01,118.1 CD18.AK2 | v19.09,147.31 18.77,147.62 v18.77,208.9 | v33.37,222.24 v33.37,208.58
  Route15 0.254: v29.88,225.09 v27.34,227.64
  Bottom 0.254: v140.69,120.64 139.42,121.91 128.94,121.91 128.31,121.27 127.67,121.27 126.4,122.54 108.3,122.54 105.13,125.72 54.96,125.72 33.37,147.31 v19.09,147.31 | v18.77,208.9 19.09,208.58 v33.37,208.58 | v33.37,222.24 30.52,225.09 v29.88,225.09 | v27.34,227.64 27.02,227.32 23.21,227.32 22.58,227.95 22.58,233.67 32.42,233.67 33.37,234.62 35.91,234.62 A26.R2
W08  (via drill 0.61)
  Top 0.254: v143.55,111.43 143.55,113.02 144.18,113.65 CD18.AL1 | v21.31,146.36 19.4,148.26 19.4,207.63 v21.31,209.54 | v38.14,213.98 39.09,214.93 v39.09,223.19 | v39.41,228.9 39.41,231.13 A26.S2
  Route2 0.254: v36.55,225.73 36.55,226.05 v39.41,228.9
  Bottom 0.254: v143.55,111.43 141.96,109.84 131.16,109.84 130.85,110.16 129.58,110.16 129.26,109.84 57.82,109.84 v21.31,146.36 | v21.31,209.54 21.63,209.22 32.42,209.22 37.18,213.98 v38.14,213.98 | v39.09,223.19 v36.55,225.73
W09  (via drill 0.61)
  Top 0.254: v37.18,223.83 37.5,224.14 37.5,227.32 36.87,227.95 A26.T2 | v42.9,218.11 43.22,217.79 v43.22,204.77 | v61,182.23 60.68,181.92 60.68,132.39 63.22,129.84 63.22,71.74 v70.84,64.12 | v133.07,54.28 133.7,54.28 133.7,54.6 135.29,56.18 v135.29,57.14
  Route15 0.254: v42.9,218.11 v37.18,223.83
  Bottom 0.254: v43.22,204.77 45.44,202.55 47.03,202.55 57.5,192.08 57.5,182.23 v61,182.23 | v70.84,64.12 79.73,55.23 132.12,55.23 v133.07,54.28 | v135.29,57.14 CD18.BF2
W+UTS  (via drill 0.61)
  Top 0.254: v209.27,109.84 209.27,114.92 208.95,115.24 208.95,119.69 209.27,120 209.27,142.86 204.19,147.94 204.19,154.29 202.92,155.56 202.92,161.28 v201.33,162.86 | v197.2,165.4 196.57,166.04 196.57,227.95 196.89,228.27 196.89,230.18 196.57,230.49 v196.57,250.49 | A15.A1 185.46,275.58 183.87,273.99 183.87,269.86 180.69,266.69 180.69,262.56 179.74,261.61 179.74,257.8 A15.H2
  Bottom 0.254: v209.27,109.84 211.81,109.84 212.44,110.48 216.57,110.48 216.89,110.8 C12.M2 | v201.33,162.86 198.79,165.4 v197.2,165.4 | v196.57,250.49 194.98,252.08 187.36,252.08 182.6,256.85 180.06,256.85 A15.H2
W-INH\  (via drill 0.61)
  Top 0.254: v266.42,195.57 266.42,197.47 266.1,197.79 266.1,200.65 266.42,200.96 266.42,203.82 265.15,205.09 A08.V2 | v238.16,196.2 236.57,196.2 v236.57,195.25 | v224.19,190.49 224.19,187.95 B12.H1
  Route2 0.254: v228.32,193.98 227.68,193.98 v224.19,190.49
  Bottom 0.254: B12.H1 224.19,186.68 224.19,182.23 224.51,182.23 226.41,180.33 227.37,180.33 229.59,178.11 232.76,178.11 B11.L1 | v266.42,195.57 262.61,195.57 261.97,196.2 260.07,196.2 258.8,194.93 244.51,194.93 243.88,195.57 238.8,195.57 v238.16,196.2 | v236.57,195.25 236.26,194.93 229.27,194.93 v228.32,193.98
WB00  (via drill 0.61)
  Top 0.254: v81.95,238.43 82.9,239.38 v82.9,240.97 | v109.89,170.8 108.3,172.39 108.3,212.71 108.62,213.03 108.62,223.83 105.13,227.32 105.13,238.11 102.91,240.33 100.37,240.33 100.37,240.65 A21.N2 | v194.66,138.1 194.66,136.2 194.03,135.56 194.03,132.7 194.35,132.39 194.35,128.26 194.98,127.62 C14.F1 | v170.22,142.55 167.99,144.77 167.99,156.83 162.28,162.55 162.28,167.95 v162.6,168.26 | v259.12,67.61 260.07,68.57 260.07,70.79 261.66,72.38 D09.A1 | v240.7,61.27 241.02,60.95 241.02,47.61 238.48,45.07 238.48,37.45 238.8,37.14 v238.8,33.32 | v213.08,29.83 212.44,29.2 v212.44,16.82 | v97.19,19.35 95.6,20.94 95.6,99.36 94.97,100 94.97,151.75 95.29,152.07 95.29,159.05 95.92,159.69 95.92,160.96 95.6,161.28 95.6,168.9 v96.56,169.85
  Route15 0.254: v194.66,138.1 194.66,138.42 194.03,139.05 194.03,141.27 v194.66,141.91 | v259.12,67.61 255.94,64.44 255.62,64.76 v255.31,64.76
  Bottom 0.254: v81.95,238.43 80.36,236.84 54.01,236.84 53.06,237.8 A25.P2 | v82.9,240.97 83.22,241.29 85.44,241.29 87.03,242.87 95.6,242.87 96.87,241.61 99.41,241.61 A21.N2 | v194.66,141.91 194.35,141.59 192.76,141.59 192.44,141.27 190.22,141.27 189.9,141.59 180.06,141.59 179.74,141.27 177.52,141.27 176.88,141.91 174.03,141.91 173.71,141.59 171.17,141.59 v170.22,142.55 | v162.6,168.26 161.33,169.53 140.37,169.53 138.78,171.12 B18.N2 137.51,171.12 136.56,170.17 110.53,170.17 v109.89,170.8 109.57,170.49 107.99,170.49 107.67,170.17 96.87,170.17 v96.56,169.85 | v255.31,64.76 250.86,64.76 250.23,64.12 247.37,64.12 246.73,64.76 244.19,64.76 v240.7,61.27 | v238.8,33.32 235.3,29.83 v213.08,29.83 | v212.44,16.82 212.13,16.5 181.96,16.5 181.33,17.13 178.15,17.13 177.52,16.5 110.84,16.5 109.57,17.77 98.78,17.77 v97.19,19.35
WB00\  (via drill 0.61)
  Top 0.254: v108.3,169.53 107.67,170.17 107.67,213.03 107.99,213.35 107.99,223.51 104.49,227 104.49,236.52 103.54,237.48 A21.P2 | v144.18,122.22 143.23,123.18 143.23,150.8 142.59,151.43 142.59,166.68 141.64,167.63 B18.P2
  Route2 0.254: v183.55,123.81 v188.95,129.21
  Route15 0.254: v208.32,129.21 211.17,132.07 v214.03,129.21
  Bottom 0.254: v208.32,129.21 208,128.89 200.06,128.89 199.11,129.84 C14.E1 197.84,129.84 196.89,128.89 189.27,128.89 v188.95,129.21 | v214.03,129.21 214.35,128.89 232.13,128.89 235.3,132.07 240.38,132.07 241.34,133.02 245.46,133.02 C10.D1 | v108.3,169.53 135.61,169.53 136.24,168.9 140.37,168.9 140.69,168.58 B18.P2 | v183.55,123.81 182.28,122.54 164.18,122.54 163.55,121.91 144.5,121.91 v144.18,122.22
WB01  (via drill 0.61)
  Top 0.254: v33.69,176.52 32.1,178.11 32.1,207.31 32.42,207.63 32.42,224.46 32.1,224.78 32.1,228.27 v33.69,229.86 | v164.18,143.18 162.28,145.08 162.28,154.29 v162.6,154.61 | v122.59,152.71 121.96,152.07 v121.96,150.8 | v114.02,149.85 114.02,163.5 114.65,164.14 114.65,171.12 v114.97,171.44 | v233.72,46.66 232.13,45.07 232.13,35.55 v232.45,35.23 | v92.43,30.47 92.43,60.31 93.06,60.95 93.06,62.22 92.43,62.85 92.43,87.3 91.79,87.94 v91.79,147.31
  Route2 0.254: v236.89,50.79 236.89,49.83 v233.72,46.66
  Route15 0.254: v170.22,141.27 188.63,122.86 188.63,121.27 C14.J2
  Bottom 0.254: v33.69,176.52 72.43,176.52 76.24,172.71 107.03,172.71 107.99,171.76 112.11,171.76 B20.N2 v114.97,171.44 | v33.69,229.86 34.33,230.49 42.9,230.49 47.03,234.62 48.61,234.62 A25.R2 | v170.22,141.27 169.26,142.23 167.99,142.23 167.04,141.27 166.09,141.27 v164.18,143.18 | v162.6,154.61 162.28,154.29 157.52,154.29 156.88,153.66 123.54,153.66 v122.59,152.71 | v121.96,150.8 121,149.85 v114.02,149.85 112.43,148.26 92.75,148.26 v91.79,147.31 | v236.89,50.79 237.53,50.79 242.92,56.18 245.15,56.18 245.46,55.87 253.08,55.87 254.35,57.14 D09.F1 | v232.45,35.23 230.86,33.64 188.31,33.64 187.68,34.28 187.04,34.28 186.41,33.64 177.52,33.64 176.88,33.01 173.07,33.01 170.53,30.47 v92.43,30.47
WB01\  (via drill 0.61)
  Top 0.254: v117.51,134.93 117.19,135.24 117.19,166.68 116.24,167.63 B20.P2 | v171.49,127.3 171.8,126.99 v171.8,120.96 | v256.89,101.59 257.21,101.27 257.21,86.66 v258.8,85.08 | v261.34,82.54 261.02,82.22 261.02,75.87 v258.8,73.65 | v248,70.16 247.37,69.52 v247.37,60.31 | v167.04,57.46 164.82,59.68 164.82,71.11 163.23,72.69 v163.23,84.44 | v158.15,84.76 158.47,85.08 158.47,94.6 158.79,94.92 158.79,103.49 158.47,103.81 158.47,110.48 155.93,113.02 155.93,128.58 v156.25,128.89 | v249.27,112.7 C10.K1
  Route2 0.254: v185.46,119.05 188.31,121.91 189.9,121.91 191.49,123.49 C14.H2 | v256.89,101.59 v255.62,102.86 | v247.69,72.38 248.96,71.11 v248,70.16
  Route15 0.254: v176.57,117.78 v178.47,119.69
  Bottom 0.254: v117.51,134.93 117.83,134.61 139.42,134.61 141.96,132.07 156.25,132.07 | 156.25,132.07 162.91,132.07 166.72,128.26 170.53,128.26 v171.49,127.3 | v171.8,120.96 174.98,117.78 v176.57,117.78 | v178.47,119.69 178.79,119.37 181.01,119.37 181.65,118.73 185.14,118.73 v185.46,119.05 | v249.27,112.7 248.96,112.38 248.64,112.38 244.83,108.57 244.83,106.03 253.08,106.03 254.35,104.76 254.35,102.86 v255.62,102.86 | v261.34,82.54 v258.8,85.08 | v258.8,73.65 256.58,71.43 253.72,71.43 253.4,71.74 248.32,71.74 v247.69,72.38 | v247.37,60.31 246.1,59.04 239.75,59.04 239.11,59.68 237.84,59.68 237.21,59.04 232.76,59.04 230.22,56.5 228.32,56.5 227.68,55.87 224.51,55.87 221.97,58.41 204.82,58.41 202.28,55.87 168.63,55.87 v167.04,57.46 | v163.23,84.44 162.91,84.76 v158.15,84.76 | v156.25,128.89 156.25,132.07
WB02  (via drill 0.61)
  Top 0.254: v49.57,250.18 49.57,249.23 50.52,248.27 50.52,238.11 51.79,236.84 51.79,232.71 52.11,232.4 A25.S2 | v111.8,249.23 111.48,248.91 111.48,242.87 112.43,241.92 A20.N2 | v256.58,31.42 256.58,30.47 259.43,30.47 260.07,31.1 260.07,34.91 261.02,35.86 261.02,39.99 261.66,40.63 D09.M1 | v252.77,28.25 251.18,26.66 251.18,14.91 v250.54,14.27 | v223.56,13.96 216.57,13.96 v216.57,20.31 | v30.52,48.57 25.12,53.96 v25.12,229.86 | v173.39,87.94 171.17,85.71 164.5,85.71 164.5,84.44 163.87,83.81 163.87,73.01 166.09,70.79 166.09,69.2 168.31,66.98 168.31,58.41 167.99,58.09 v167.99,19.35
  Route2 0.254: v256.58,31.42 255.94,31.42 v252.77,28.25 | v173.39,87.94 191.81,106.35 191.81,107.3 194.35,109.84 194.35,111.11 196.25,113.02 197.84,111.43 C14.M1
  Bottom 0.254: v49.57,250.18 51.47,252.08 60.36,252.08 62.9,249.54 87.35,249.54 87.98,248.91 111.48,248.91 v111.8,249.23 | v250.54,14.27 239.43,14.27 238.8,13.64 233.08,13.64 232.76,13.32 224.19,13.32 v223.56,13.96 | v216.57,20.31 181.96,20.31 180.06,18.4 177.52,18.4 176.88,17.77 167.99,17.77 | 167.99,17.77 130.85,17.77 130.21,18.4 126.72,18.4 126.08,17.77 110.53,17.77 107.99,20.31 58.77,20.31 v30.52,48.57 | v25.12,229.86 32.42,229.86 33.37,228.9 34.96,228.9 35.91,229.86 50.2,229.86 51.79,231.45 A25.S2 | v167.99,19.35 167.99,17.77
WB02\  (via drill 0.61)
  Top 0.254: v189.27,105.72 187.68,104.13 187.68,91.11 187.04,90.47 v187.04,70.79 | v227.05,71.74 226.73,72.06 226.73,77.14 v227.05,77.46 | v242.29,77.46 244.19,79.36 244.19,93.65 v243.88,93.97 | v246.1,97.14 C10.R1 | v115.61,228.9 115.61,229.86 114.65,230.81 114.65,232.4 115.29,233.03 115.29,237.16 115.61,237.48 A20.P2 | v84.81,228.9 82.59,226.68 v82.59,221.29 | v86.08,220.02 85.44,219.38 v85.44,207.63 | v50.52,201.28 50.52,147.94 53.69,144.77 53.69,88.89 47.66,82.86 47.66,74.28 54.01,67.93 v54.01,44.12 | v144.5,35.23 v140.37,39.36 | v149.9,34.91 152.75,34.91 152.75,34.28 153.39,33.64 155.61,33.64 v155.61,38.72 | v165.14,41.9 v163.23,39.99 | v184.19,44.12 183.87,44.44 183.87,66.66 v183.55,66.98
  Route2 0.254: v189.27,105.72 193.71,110.16 193.71,111.43 194.98,112.7 194.98,113.65 C14.L1 | v243.88,93.97 243.88,94.92 v246.1,97.14
  Route15 0.254: v108.62,227.95 107.67,227.95 105.45,225.73 v103.54,227.64
  Bottom 0.254: v187.04,70.79 187.04,68.25 | 187.04,68.25 194.03,68.25 194.35,67.93 204.19,67.93 204.51,68.25 206.73,68.25 207.05,67.93 216.89,67.93 217.52,68.57 222.29,68.57 225.46,71.74 v227.05,71.74 | v227.05,77.46 227.37,77.14 241.97,77.14 v242.29,77.46 | v115.61,228.9 114.02,227.32 111.48,227.32 110.84,227.95 v108.62,227.95 | v103.54,227.64 103.22,227.32 86.71,227.32 85.13,228.9 v84.81,228.9 | v82.59,221.29 83.86,220.02 v86.08,220.02 | v85.44,207.63 85.13,207.95 63.54,207.95 56.87,201.28 v50.52,201.28 | v54.01,44.12 58.77,39.36 v140.37,39.36 | v144.5,35.23 146.09,33.64 148.63,33.64 v149.9,34.91 | v155.61,38.72 156.88,39.99 v163.23,39.99 | v165.14,41.9 166.41,43.17 183.23,43.17 v184.19,44.12 | v183.55,66.98 184.82,68.25 187.04,68.25
WC  (via drill 0.61)
  Top 0.254: D11.S1 236.26,29.2 234.67,30.78 234.67,72.69 234.99,73.01 234.99,81.58 236.57,83.17 236.57,90.16 237.84,91.43 237.84,175.88 237.21,176.52 237.21,180.64 B11.K1 236.26,181.6 236.26,184.14 234.67,185.73 234.67,226.36 234.99,226.68 234.99,228.9 234.67,229.22 v234.67,283.2 | v47.34,277.48 47.34,258.75 46.39,257.8 A26.H1
  Bottom 0.254: v47.34,277.48 47.34,281.61 57.19,281.61 57.82,280.98 135.29,280.98 136.88,282.56 139.42,282.56 139.74,282.24 211.17,282.24 211.81,282.88 218.79,282.88 219.11,283.2 v234.67,283.2 | B10.M1 248.64,174.93 248.32,175.25 245.15,175.25 239.75,180.64 237.21,180.64 B11.K1
WC0  (via drill 0.61)
  Top 0.254: v318.49,108.57 320.39,110.48 320.39,114.61 v319.44,115.56 | v322.93,118.1 324.2,119.37 324.2,126.35 v325.16,127.3 | v363.89,126.67 363.89,124.45 C01.H1
  Route2 0.254: v311.82,106.35 316.27,106.35 v318.49,108.57
  Route15 0.254: v296.58,112.07 v302.3,106.35
  Bottom 0.254: v296.58,112.07 294.99,112.07 294.36,111.43 C06.M2 | v302.3,106.35 v311.82,106.35 | v319.44,115.56 319.44,116.19 319.76,116.19 321.66,118.1 v322.93,118.1 | v325.16,127.3 326.74,128.89 332.46,128.89 335,131.43 335,132.07 351.51,132.07 351.83,132.39 353.1,132.39 353.41,132.07 357.54,132.07 360.4,129.21 361.99,129.21 363.89,127.3 v363.89,126.67
WC0\  (via drill 0.61)
  Top 0.254: v234.03,28.88 234.03,30.78 233.72,31.1 D11.R1 | v239.43,29.51 237.84,31.1 237.84,34.28 238.16,34.6 238.16,35.23 235.3,38.09 235.3,45.39 v235.94,46.03 | v241.97,51.1 244.19,53.33 244.19,54.6 243.88,54.92 243.88,59.36 244.19,59.68 244.19,61.58 v243.88,61.9 | v269.28,71.43 273.72,75.87 275.63,75.87 v275.63,77.77 | v290.23,104.13 290.23,107.3 C06.N2
  Route2 0.254: v235.94,46.03 236.89,46.03 v241.97,51.1 | v257.85,61.9 259.75,61.9 v269.28,71.43 | v283.88,85.08 283.88,86.66 285.47,88.25 285.47,94.6 288.64,97.78 288.64,100.63 288.96,100.95 288.96,102.86 v290.23,104.13
  Bottom 0.254: v234.03,28.88 235.62,27.29 237.21,27.29 v239.43,29.51 | v243.88,61.9 244.83,60.95 246.73,60.95 248.64,62.85 251.18,62.85 251.81,62.22 254.04,62.22 254.67,62.85 255.31,62.85 256.26,61.9 v257.85,61.9 | v275.63,77.77 275.63,78.73 279.75,82.86 279.75,84.13 282.93,84.13 v283.88,85.08
WC\  (via drill 0.61)
  Top 0.254: D11.U1 235.94,22.53 233.72,22.53 233.72,23.16 231.81,25.07 231.81,34.6 231.49,34.91 231.49,39.68 230.54,40.63 D11.M2 | C12.T2 214.03,95.87 213.08,96.83 213.08,146.36 215.94,149.21 215.94,153.98 216.25,154.29 216.25,184.14 214.67,185.73 214.67,189.85 B12.F2 | v212.76,41.58 212.44,41.9 v212.44,84.13 | v208.63,84.44 206.73,86.35 v206.73,92.38
  Route15 0.254: v208.95,92.38 v210.86,94.28
  Bottom 0.254: v212.76,41.58 214.35,39.99 228.64,39.99 229.59,40.95 D11.M2 | v212.44,84.13 212.13,84.44 v208.63,84.44 | v206.73,92.38 v208.95,92.38 | v210.86,94.28 211.49,94.92 213.71,94.92 C12.T2
WR_EN  (via drill 0.61)
  Top 0.254: v44.17,236.52 44.17,258.75 43.22,259.7 A26.F1 | B20.R2 112.43,165.72 111.48,166.68 111.48,175.56 110.84,176.2 110.84,201.28 111.16,201.6 111.16,204.14 112.75,205.73 112.75,220.33 111.48,221.6 111.48,233.35 112.43,234.3 A20.R2 | 184.5,131.75 184.5,141.27 185.46,142.23 C15.A1 | 184.5,131.75 184.5,116.83 184.82,116.51 184.82,112.38 185.46,111.75 C15.M1 | 184.5,131.75 v185.77,131.75 | D09.N1 259.12,38.72 259.12,42.85 260.07,43.8 260.07,51.74 261.66,53.33 D09.H1 261.66,54.6 260.07,56.18 260.07,64.12 258.16,66.03 | 256.89,44.12 256.89,58.72 | 256.89,44.12 256.89,34.28 255.62,33.01 D09.S2 255.94,27.93 256.89,26.98 v256.89,15.54 | 256.89,58.72 255.94,59.68 D09.E2 | 256.89,44.12 v256.58,44.12 | 258.16,66.03 258.16,64.76 256.89,63.49 256.89,58.72 | 258.16,66.03 258.16,68.88 258.48,69.2 D09.B1 | C10.H2 243.24,123.18 244.19,122.22 244.19,96.83 242.92,95.55 C10.U2 242.29,91.74 242.29,84.76 241.34,83.81 241.34,72.69 241.65,72.38 241.65,71.11 v243.88,71.11 | v197.2,109.84 197.2,97.78 198.16,96.83 198.16,92.7 C14.U1 | v108.62,164.77 107.67,163.82 107.67,85.39 107.99,85.08 107.99,74.6 107.67,74.28 v107.67,14.59
  Bottom 0.254: A20.R2 109.57,234.94 108.3,236.21 105.76,236.21 104.81,235.26 100.68,235.26 A21.R2 99.41,235.26 96.24,235.26 95.29,236.21 88.94,236.21 88.62,236.52 82.59,236.52 82.27,236.21 44.49,236.21 v44.17,236.52 | v185.77,131.75 186.09,131.43 208,131.43 209.27,132.7 213.4,132.7 213.71,133.02 C12.D2 | v256.58,44.12 253.08,44.12 D09.L2 | C14.U1 199.11,92.38 199.43,92.7 203.55,92.7 204.19,93.33 238.16,93.33 239.11,92.38 242.29,92.38 C10.U2 | v243.88,71.11 253.08,71.11 253.4,70.79 257.53,70.79 258.16,70.16 D09.B1 | v197.2,109.84 187.36,109.84 186.41,110.8 C15.M1 | v108.62,164.77 112.11,164.77 B20.R2 | v107.67,14.59 107.67,13.32 114.97,13.32 116.24,12.05 220.06,12.05 223.87,15.86 256.58,15.86 v256.89,15.54
WR_EN\  (via drill 0.61)
  Top 0.254: v200.06,123.49 199.74,123.18 199.74,100 198.79,99.05 C14.S1 | v182.28,131.43 181.96,131.11 181.96,129.21 179.74,126.99 179.74,124.45 C15.H2 | v228.64,191.76 227.37,193.03 227.37,194.93 v229.91,197.47 | v217.52,210.17 v219.75,207.95 | v208.63,217.79 204.82,221.6 v204.82,222.87 | v158.47,226.68 158.47,218.74 158.79,218.43 158.79,207.63 158.47,207.31 158.47,168.26 155.93,165.72 155.93,151.75 157.52,150.17 v157.52,141.91 | v233.4,193.03 B11.F1
  Route15 0.254: v229.91,197.47 229.91,197.79 v219.75,207.95 | v167.68,140.01 172.44,135.24 174.03,135.24 175.61,133.65 C15.D2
